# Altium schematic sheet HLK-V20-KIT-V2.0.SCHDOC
size A4
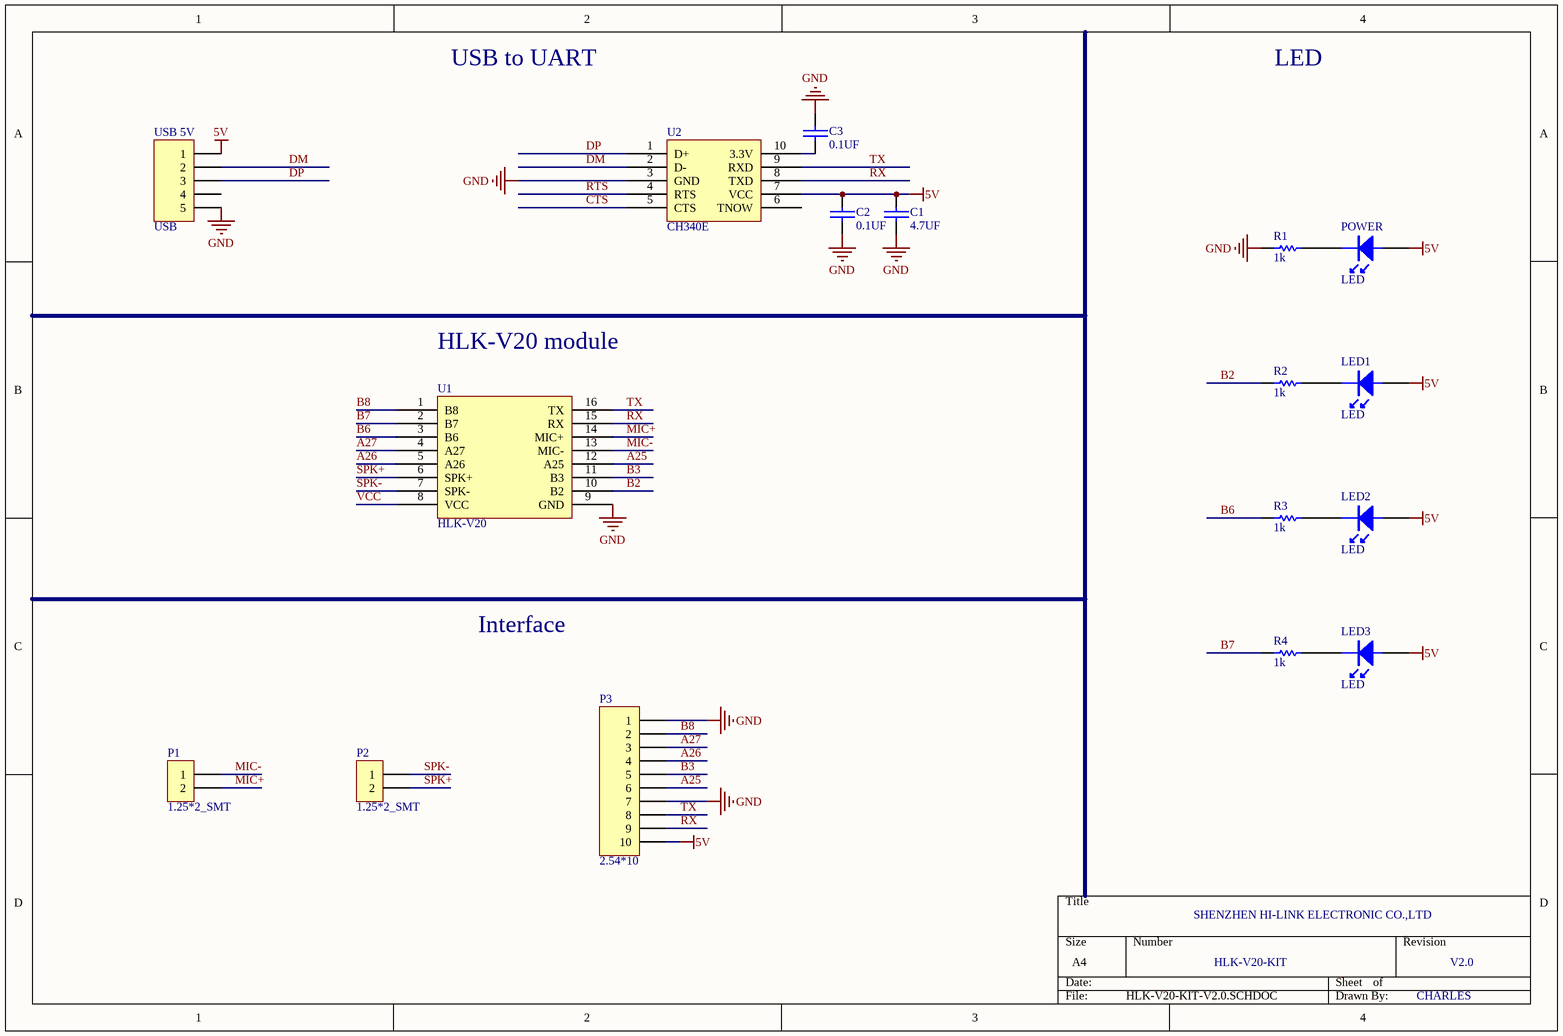
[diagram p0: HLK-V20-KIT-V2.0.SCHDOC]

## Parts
C1  4.7UF
C2  0.1UF
C3  0.1UF
LED1  LED  [LED0805]
LED2  LED  [LED0805]
LED3  LED  [LED0805]
P1  1.25*2_SMT
P2  1.25*2_SMT
P3  2.54*10  [HDR1X10]
POWER  LED  [LED0805]
R1  value 1k  [0603]  (hidden comment: Res1)
R2  value 1k  [0603]  (hidden comment: Res1)
R3  value 1k  [0603]  (hidden comment: Res1)
R4  value 1k  [0603]  (hidden comment: Res1)
U1  HLK-V20  [HLK-V20]
U2  CH340E  [MSOP-10]
USB_5V  USB  [MICRO_USB]

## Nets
5V: C1.2 C2.2 LED1.1 LED2.1 LED3.1 P3.10 POWER.1 U2.7(VCC) USB_5V.1
GND: C1.1 C2.1 C3.1 P3.1 P3.7 R1.2 U1.9(GND) U2.3(GND) USB_5V.5
A25: P3.6 U1.12(A25)
A26: P3.4 U1.5(A26)
A27: P3.3 U1.4(A27)
B2: R2.2 U1.10(B2)
B3: P3.5 U1.11(B3)
B6: R3.2 U1.3(B6)
B7: R4.2 U1.2(B7)
B8: P3.2 U1.1(B8)
CTS: U2.5(CTS)
DM: U2.2(D-) USB_5V.2
DP: U2.1(D+) USB_5V.3
MIC+: P1.2 U1.14(MIC+)
MIC-: P1.1 U1.13(MIC-)
RTS: U2.4(RTS)
RX: P3.9 U1.15(RX) U2.8(TXD)
SPK+: P2.2 U1.6(SPK+)
SPK-: P2.1 U1.7(SPK-)
TX: P3.8 U1.16(TX) U2.9(RXD)
VCC: U1.8(VCC)
NetC3_2: C3.2 U2.10(3.3V)
NetLED1_2: LED1.2 R2.1
NetLED2_2: LED2.2 R3.1
NetLED3_2: LED3.2 R4.1
NetPOWER_2: POWER.2 R1.1

Not connected (* = marked no-connect by the designer): U2 6(TNOW); USB_5V 4

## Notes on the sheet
- USB to UART
- LED
- HLK-V20 module
- Interface
- SHENZHEN HI-LINK ELECTRONIC CO.,LTD
- HLK-V20-KIT
- V2.0
- CHARLES

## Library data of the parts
C1-C3 = CAP: Capacitor
P1 P2 = CON2: Connector
P3 = Header 10: Header, 10-Pin
R1-R4 = Res1: Resistor
U1 = HLK-V20: HLK-V20语音模块
USB_5V = Header 5: Header, 5-Pin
